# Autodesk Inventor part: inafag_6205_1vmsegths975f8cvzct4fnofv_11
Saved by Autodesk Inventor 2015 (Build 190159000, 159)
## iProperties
Company: TraceParts S.A.
Created: 2012-12
Part Number: inafag_6205_1vmsegths975f8cvzct4fnofv_11
Checked By: TraceParts S.A.
Catalog Web Link: www.traceparts.com
Document SubType Name: Modeling
Designer: TraceParts
Material: Generic
Density: 1 g/cm^3
Appearance: Default
Author: TraceParts
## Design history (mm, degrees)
feature "inafag_6205_1vmsegths975f8cvzct4fnofv"
body "Solid1"
